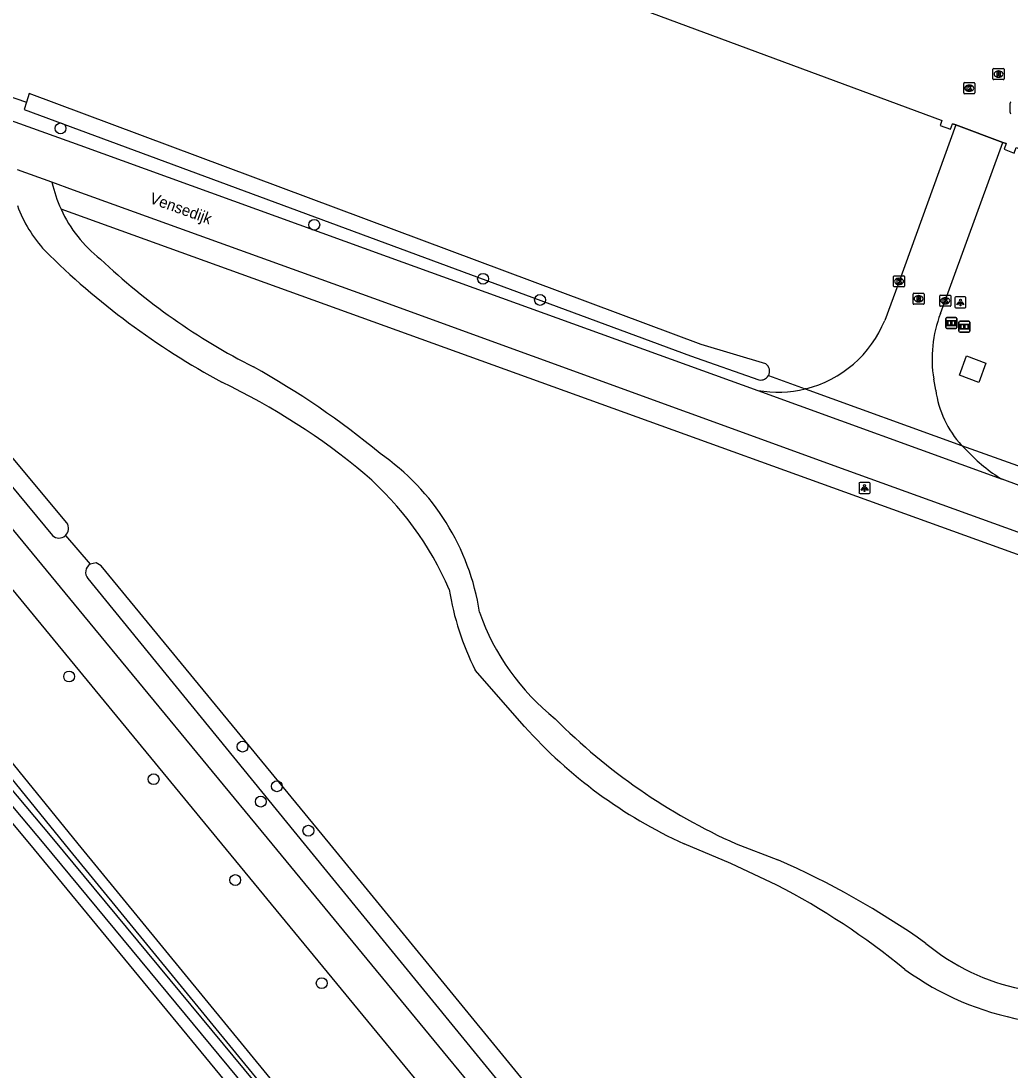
# Model space of a CAD drawing. Extents: x 156061 to 157804, y 383451 to 385640.
# Drawn here: x 156629.3 to 156718.3, y 384979.6 to 385074 of the extents above; entities that cross this region are included whole.
import ezdxf

# ---------------------------------------------------------------- set-up
doc = ezdxf.new("R2010")
doc.units = 0
for name, color, linetype in [('IMGEO_Berm_groen', 7, 'Continuous'), ('IMGEO_Boom', 7, 'Continuous'), ('IMGEO_Fietspad_gesloten', 7, 'Continuous'), ('IMGEO_Grasland_overig', 7, 'Continuous'), ('IMGEO_Groenvoorziening', 7, 'Continuous'), ('IMGEO_Hek', 7, 'Continuous'), ('IMGEO_Informatiebord', 7, 'Continuous'), ('IMGEO_Kolk', 7, 'Continuous'), ('IMGEO_Lage_trafo', 7, 'Continuous'), ('IMGEO_Lichtpunt', 7, 'Continuous'), ('IMGEO_Loofbos', 7, 'Continuous'), ('IMGEO_Openbare_ruimte_label', 7, 'Continuous'), ('IMGEO_Rijbaan_lokaal_open', 7, 'Continuous'), ('IMGEO_Rioolput', 7, 'Continuous'), ('IMGEO_Waterloop', 7, 'Continuous')]:
    doc.layers.add(name, color=color, linetype=linetype)

msp = doc.modelspace()

# ---------------------------------------------------------------- linework, layer by layer
at = {"layer": 'IMGEO_Berm_groen'}
msp.add_lwpolyline([(156633.293, 385027.733), (156635.536, 385025.155)], dxfattribs=at)
at = {"layer": 'IMGEO_Boom'}
for centre in [(156632.856, 385064.382), (156655.692, 385055.706), (156670.884, 385050.847), (156676.018, 385048.942), (156633.634, 385015.06), (156649.236, 385008.753), (156641.232, 385005.82), (156652.326, 385005.179), (156650.88, 385003.8), (156655.162, 385001.18), (156648.58, 384996.739), (156656.369, 384987.464)]:
    msp.add_circle(centre, 0.489, dxfattribs=at)
at = {"layer": 'IMGEO_Fietspad_gesloten'}
for points in [[(156952.011, 384636.1), (156951.649, 384636.454), (156945.248, 384644.122), (156913.262, 384682.917), (156857.952, 384750), (156766.231, 384861.244), (156717.241, 384920.698), (156651.898, 385000), (156634.534, 385021.048), (156628.661, 385028.193), (156628.314, 385028.596), (156616.132, 385043.374), (156611.412, 385049.1), (156600.259, 385062.638)], [(156605.091, 385050.034), (156608.817, 385046.509), (156609.374, 385045.976), (156609.93, 385045.436), (156647.34, 385000), (156714.453, 384918.502), (156763.606, 384858.813), (156853.32, 384750), (156910.525, 384680.616)]]:
    msp.add_lwpolyline(points, dxfattribs=at)
at = {"layer": 'IMGEO_Grasland_overig'}
msp.add_arc((156643.914, 385062.172), 12.118, 192.57556, 204.6773, dxfattribs=at)
at = {"layer": 'IMGEO_Groenvoorziening'}
for points in [[(156717.677, 385063.118), (156717.97, 385063.009), (156717.781, 385062.506), (156718.696, 385062.163), (156718.88, 385062.654), (156870.373, 385006.508), (156870.967, 385006.288), (156875.119, 385016.625), (156892.549, 385064.295), (156865.99, 385088.285), (156852.111, 385101.789), (156804.773, 385147.48), (156780.437, 385174.157), (156759.871, 385196.529)], [(156704.185, 384910.355), (156680.539, 384938.812), (156675.709, 384944.624), (156664.3, 384958.479), (156630.109, 385000), (156603.329, 385032.022), (156590.034, 385048.185), (156581.376, 385058.421), (156579.11, 385060.987), (156576.247, 385063.649), (156574.166, 385065.132), (156572.592, 385066.255), (156568.65, 385068.402), (156563.107, 385070.714), (156551.893, 385074.785), (156500, 385093.06), (156436.131, 385115.542), (156397.25, 385072.572), (156397.423, 385071.829)], [(156566.301, 385089.228), (156607.493, 385074.38), (156629.792, 385066.728)], [(156658.244, 385085.094), (156712.128, 385065.114), (156712.188, 385065.092), (156712.024, 385064.637), (156712.959, 385064.3), (156713.142, 385064.807), (156713.445, 385064.694)], [(156673.482, 384950.407), (156672.799, 384949.599), (156658.27, 384967.539), (156631.387, 385000), (156602.972, 385033.813), (156586.855, 385053.4), (156580.462, 385060.696), (156577.709, 385063.589)], [(156582.153, 385063.43), (156585.552, 385059.831), (156605.373, 385035.73), (156634.41, 385000), (156674.271, 384951.339), (156673.482, 384950.407)], [(156696.567, 385042.138), (156699.886, 385040.939)], [(156713.959, 385035.854), (156720.234, 385033.587)]]:
    msp.add_lwpolyline(points, dxfattribs=at)
at = {"layer": 'IMGEO_Hek'}
for points in [[(156658.244, 385085.094), (156712.128, 385065.114), (156712.188, 385065.092)], [(156713.445, 385064.694), (156713.142, 385064.807)], [(156717.677, 385063.118), (156713.445, 385064.694)], [(156717.97, 385063.009), (156717.677, 385063.118)]]:
    msp.add_lwpolyline(points, dxfattribs=at)
at = {"layer": 'IMGEO_Informatiebord'}
for p, q in [((156712.535, 385046.462), (156712.535, 385047.262)), ((156712.535, 385047.262), (156712.535, 385046.462)), ((156712.635, 385047.362), (156713.425, 385047.362)), ((156713.425, 385047.362), (156712.635, 385047.362)), ((156713.525, 385047.262), (156713.525, 385046.462)), ((156713.525, 385046.462), (156713.525, 385047.262)), ((156713.425, 385046.362), (156712.635, 385046.362)), ((156712.635, 385046.362), (156713.425, 385046.362)), ((156713.712, 385046.139), (156713.712, 385046.939)), ((156713.712, 385046.939), (156713.712, 385046.139)), ((156713.812, 385047.039), (156714.602, 385047.039)), ((156714.602, 385047.039), (156713.812, 385047.039)), ((156714.702, 385046.939), (156714.702, 385046.139)), ((156714.702, 385046.139), (156714.702, 385046.939)), ((156714.602, 385046.039), (156713.812, 385046.039)), ((156713.812, 385046.039), (156714.602, 385046.039))]:
    msp.add_line(p, q, dxfattribs=at)
for points in [[(156712.636, 385047.094), (156713.424, 385047.094), (156713.424, 385046.63), (156712.636, 385046.63), (156712.636, 385047.094)], [(156712.701, 385047.029), (156712.701, 385046.695), (156712.976, 385046.695), (156712.977, 385046.908), (156713.081, 385046.909), (156713.082, 385046.695), (156713.359, 385046.695), (156713.359, 385047.029), (156713.083, 385047.029), (156713.083, 385046.949), (156712.977, 385046.949), (156712.977, 385047.029), (156712.701, 385047.029)], [(156713.813, 385046.771), (156714.601, 385046.771), (156714.601, 385046.307), (156713.813, 385046.307), (156713.813, 385046.771)], [(156713.878, 385046.706), (156713.878, 385046.372), (156714.153, 385046.372), (156714.154, 385046.585), (156714.258, 385046.586), (156714.259, 385046.372), (156714.536, 385046.372), (156714.536, 385046.706), (156714.26, 385046.706), (156714.26, 385046.626), (156714.154, 385046.626), (156714.154, 385046.706), (156713.878, 385046.706)]]:
    msp.add_lwpolyline(points, dxfattribs=at)
for centre, start, end in [((156712.635, 385047.262), 90, 180), ((156712.635, 385047.262), 90, 180), ((156713.425, 385047.262), 0, 90), ((156713.425, 385047.262), 360, 90), ((156712.635, 385046.462), 180, 270), ((156712.635, 385046.462), 180, 270), ((156713.425, 385046.462), 270, 0), ((156713.425, 385046.462), 270, 0), ((156713.812, 385046.939), 90, 180), ((156713.812, 385046.939), 90, 180), ((156714.602, 385046.939), 0, 90), ((156714.602, 385046.939), 360, 90), ((156713.812, 385046.139), 180, 270), ((156713.812, 385046.139), 180, 270), ((156714.602, 385046.139), 270, 0), ((156714.602, 385046.139), 270, 0)]:
    msp.add_arc(centre, 0.1, start, end, dxfattribs=at)
at = {"layer": 'IMGEO_Kolk'}
for p, q in [((156714.145, 385067.574), (156714.145, 385068.426)), ((156714.22, 385068.5), (156715.072, 385068.5)), ((156714.633, 385068.28), (156714.658, 385068.28)), ((156715.146, 385068.426), (156715.146, 385067.574)), ((156715.072, 385067.5), (156714.22, 385067.5)), ((156714.656, 385067.72), (156714.631, 385067.72)), ((156718.312, 385065.807), (156718.312, 385066.659)), ((156707.822, 385050.193), (156707.822, 385051.045)), ((156707.897, 385051.119), (156708.749, 385051.119)), ((156708.823, 385051.045), (156708.823, 385050.193)), ((156708.749, 385050.119), (156707.897, 385050.119)), ((156708.333, 385050.339), (156708.308, 385050.339)), ((156708.31, 385050.899), (156708.335, 385050.899)), ((156711.986, 385048.448), (156711.986, 385049.3)), ((156712.061, 385049.374), (156712.913, 385049.374)), ((156712.474, 385049.154), (156712.499, 385049.154)), ((156712.987, 385049.3), (156712.987, 385048.448)), ((156712.913, 385048.374), (156712.061, 385048.374)), ((156712.497, 385048.594), (156712.472, 385048.594))]:
    msp.add_line(p, q, dxfattribs=at)
for points in [[(156714.145, 385067.574), (156714.145, 385068.426)], [(156714.22, 385068.5), (156715.072, 385068.5)], [(156714.466, 385068.2), (156714.589, 385068.2), (156714.589, 385068.049), (156714.719, 385068.2), (156714.883, 385068.2), (156714.737, 385068.049), (156714.89, 385067.8), (156714.738, 385067.8), (156714.653, 385067.964), (156714.589, 385067.897), (156714.589, 385067.8), (156714.466, 385067.8), (156714.466, 385068.2)], [(156715.146, 385068.426), (156715.146, 385067.574)], [(156715.072, 385067.5), (156714.22, 385067.5)], [(156718.312, 385065.807), (156718.312, 385066.659)], [(156707.822, 385050.193), (156707.822, 385051.045)], [(156707.897, 385051.119), (156708.749, 385051.119)], [(156708.823, 385051.045), (156708.823, 385050.193)], [(156708.749, 385050.119), (156707.897, 385050.119)], [(156708.143, 385050.819), (156708.266, 385050.819), (156708.266, 385050.668), (156708.396, 385050.819), (156708.56, 385050.819), (156708.414, 385050.668), (156708.567, 385050.419), (156708.415, 385050.419), (156708.33, 385050.583), (156708.266, 385050.516), (156708.266, 385050.419), (156708.143, 385050.419), (156708.143, 385050.819)], [(156711.986, 385048.448), (156711.986, 385049.3)], [(156712.061, 385049.374), (156712.913, 385049.374)], [(156712.987, 385049.3), (156712.987, 385048.448)], [(156712.913, 385048.374), (156712.061, 385048.374)], [(156712.307, 385049.074), (156712.43, 385049.074), (156712.43, 385048.923), (156712.56, 385049.074), (156712.724, 385049.074), (156712.578, 385048.923), (156712.731, 385048.674), (156712.579, 385048.674), (156712.494, 385048.838), (156712.43, 385048.771), (156712.43, 385048.674), (156712.307, 385048.674), (156712.307, 385049.074)]]:
    msp.add_lwpolyline(points, dxfattribs=at)
for centre, start, end in [((156714.222, 385068.424), 91.55205, 178.44795), ((156714.222, 385068.424), 91.55205, 178.44795), ((156715.07, 385068.424), 1.55205, 88.44795), ((156715.07, 385068.424), 1.55205, 88.44795), ((156714.222, 385067.576), 181.55205, 268.44795), ((156714.222, 385067.576), 181.55205, 268.44795), ((156715.07, 385067.576), 271.55205, 358.44795), ((156715.07, 385067.576), 271.55205, 358.44795), ((156718.389, 385066.657), 91.55205, 178.44795), ((156718.389, 385066.657), 91.55205, 178.44795), ((156718.389, 385065.809), 181.55205, 268.44795), ((156718.389, 385065.809), 181.55205, 268.44795), ((156707.899, 385051.043), 91.55205, 178.44795), ((156707.899, 385051.043), 91.55205, 178.44795), ((156708.747, 385051.043), 1.55205, 88.44795), ((156708.747, 385051.043), 1.55205, 88.44795), ((156707.899, 385050.195), 181.55205, 268.44795), ((156707.899, 385050.195), 181.55205, 268.44795), ((156708.747, 385050.195), 271.55205, 358.44795), ((156708.747, 385050.195), 271.55205, 358.44795), ((156712.063, 385049.298), 91.55205, 178.44795), ((156712.063, 385049.298), 91.55205, 178.44795), ((156712.911, 385049.298), 1.55205, 88.44795), ((156712.911, 385049.298), 1.55205, 88.44795), ((156712.063, 385048.45), 181.55205, 268.44795), ((156712.063, 385048.45), 181.55205, 268.44795), ((156712.911, 385048.45), 271.55205, 358.44795), ((156712.911, 385048.45), 271.55205, 358.44795)]:
    msp.add_arc(centre, 0.0765, start, end, dxfattribs=at)
for centre, major_axis, ratio, start_param, end_param in [((156714.632, 385068), (-0.387, 0.002), 0.722429, 4.712389, 7.853982), ((156714.657, 385068), (-0.39, 0.002), 0.717154, 1.570796, 4.712389), ((156708.309, 385050.619), (-0.387, 0.002), 0.722429, 4.712389, 7.853982), ((156708.334, 385050.619), (-0.39, 0.002), 0.717154, 1.570796, 4.712389), ((156712.473, 385048.874), (-0.387, 0.002), 0.722429, 4.712389, 7.853982), ((156712.498, 385048.874), (-0.39, 0.002), 0.717154, 1.570796, 4.712389)]:
    msp.add_ellipse(centre, major_axis=major_axis, ratio=ratio, start_param=start_param, end_param=end_param, dxfattribs=at)
at = {"layer": 'IMGEO_Lage_trafo'}
msp.add_lwpolyline([(156716.143, 385043.251), (156715.495, 385041.518), (156713.757, 385042.168), (156714.405, 385043.901), (156716.143, 385043.251)], dxfattribs=at)
at = {"layer": 'IMGEO_Lichtpunt'}
for p, q in [((156713.352, 385049.124), (156713.352, 385048.317)), ((156713.352, 385049.124), (156713.352, 385048.317)), ((156714.254, 385049.219), (156713.446, 385049.219)), ((156714.254, 385049.219), (156713.446, 385049.219)), ((156714.348, 385048.317), (156714.348, 385049.124)), ((156714.348, 385048.317), (156714.348, 385049.124)), ((156713.446, 385048.223), (156714.254, 385048.223)), ((156713.446, 385048.223), (156714.254, 385048.223)), ((156704.721, 385032.426), (156704.721, 385031.619)), ((156704.721, 385032.426), (156704.721, 385031.619)), ((156705.623, 385032.521), (156704.815, 385032.521)), ((156705.623, 385032.521), (156704.815, 385032.521)), ((156705.717, 385031.619), (156705.717, 385032.426)), ((156705.717, 385031.619), (156705.717, 385032.426)), ((156704.815, 385031.525), (156705.623, 385031.525)), ((156704.815, 385031.525), (156705.623, 385031.525))]:
    msp.add_line(p, q, dxfattribs=at)
for points in [[(156713.726, 385048.788), (156713.765, 385048.76), (156713.577, 385048.498), (156713.539, 385048.525), (156713.726, 385048.788)], [(156713.828, 385048.74), (156713.875, 385048.74), (156713.875, 385048.418), (156713.828, 385048.418), (156713.828, 385048.74)], [(156713.938, 385048.76), (156713.976, 385048.787), (156714.163, 385048.525), (156714.124, 385048.497), (156713.938, 385048.76)], [(156705.095, 385032.09), (156705.134, 385032.062), (156704.946, 385031.8), (156704.908, 385031.827), (156705.095, 385032.09)], [(156705.197, 385032.042), (156705.244, 385032.042), (156705.244, 385031.72), (156705.197, 385031.72), (156705.197, 385032.042)], [(156705.307, 385032.062), (156705.345, 385032.089), (156705.532, 385031.827), (156705.493, 385031.799), (156705.307, 385032.062)]]:
    msp.add_lwpolyline(points, dxfattribs=at)
for centre in [(156713.851, 385048.922), (156705.22, 385032.224)]:
    msp.add_circle(centre, 0.0994, dxfattribs=at)
for centre, start, end in [((156713.446, 385049.124), 90, 180), ((156713.446, 385049.124), 90, 180), ((156714.254, 385049.124), 0, 90), ((156714.254, 385049.124), 0, 90), ((156713.446, 385048.317), 180, 270), ((156713.446, 385048.317), 180, 270), ((156714.254, 385048.317), 270, 0), ((156714.254, 385048.317), 270, 360), ((156704.815, 385032.426), 90, 180), ((156704.815, 385032.426), 90, 180), ((156705.623, 385032.426), 0, 90), ((156705.623, 385032.426), 0, 90), ((156704.815, 385031.619), 180, 270), ((156704.815, 385031.619), 180, 270), ((156705.623, 385031.619), 270, 0), ((156705.623, 385031.619), 270, 360)]:
    msp.add_arc(centre, 0.0946, start, end, dxfattribs=at)
at = {"layer": 'IMGEO_Loofbos'}
for points in [[(156799.556, 384996.608), (156756.361, 385012.544), (156632.902, 385057.113)], [(156674.621, 385010.559), (156670.182, 385015.637)], [(156697.315, 384996.29), (156693.188, 384998.237), (156688.978, 385000)], [(156693.651, 385000), (156697.403, 384998.574)]]:
    msp.add_lwpolyline(points, dxfattribs=at)
for centre, radius, start, end in [((156640.277, 385061.528), 12.014, 199.92856, 222.69113), ((156643.961, 385062.187), 12.167, 204.64837, 231.85835), ((156680.809, 385103.134), 70.085, 225.22503, 241.50853), ((156676.67, 385095.125), 58.522, 226.58108, 243.14024), ((156613.824, 384977.458), 74.902, 50.35651, 60.91962), ((156621.297, 384986.787), 60.645, 50.02945, 64.52979), ((156649.497, 385017.591), 21.32, 8.76662, 55.37233), ((156641.331, 385011.478), 28.857, 23.28741, 49.02038), ((156692.369, 385026.818), 24.845, 189.10609, 206.74597), ((156690.616, 385027.857), 21.241, 199.28952, 231.41181), ((156707.158, 385039.76), 43.719, 221.90655, 245.42746), ((156715.911, 385049.614), 54.379, 224.86366, 245.83574), ((156666.635, 384928.442), 76.585, 54.82942, 66.31249), ((156666.692, 384937.194), 66.559, 50.6907, 62.60765), ((156723.144, 385005.922), 19.364, 230.20006, 258.58582), ((156724.179, 385009.804), 26.084, 234.03093, 259.61358)]:
    msp.add_arc(centre, radius, start, end, dxfattribs=at)
at = {"layer": 'IMGEO_Rijbaan_lokaal_open'}
for points in [[(156604.139, 385073.809), (156606.916, 385072.811), (156634.591, 385062.861), (156662.26, 385052.848), (156695.623, 385040.804)], [(156713.445, 385064.694), (156708.324, 385050.618), (156707.035, 385047.107)], [(156713.445, 385064.694), (156717.677, 385063.118)], [(156712.05, 385047.718), (156717.677, 385063.118)], [(156632.086, 385059.534), (156628.997, 385060.649)], [(156799.582, 384998.753), (156796.159, 385000), (156770.015, 385009.525), (156724.41, 385026.088), (156703.574, 385033.623), (156661.061, 385049.074), (156634.022, 385058.832), (156632.086, 385059.534)], [(156711.623, 385040.831), (156711.45, 385041.827)], [(156695.623, 385040.804), (156717.591, 385032.815)], [(156699.931, 385040.95), (156699.908, 385040.944), (156699.886, 385040.939)], [(156699.886, 385040.939), (156713.959, 385035.854)], [(156713.977, 385035.835), (156713.968, 385035.845), (156713.959, 385035.854)], [(156860.328, 384980.642), (156811.247, 384998.672), (156807.534, 385000.027), (156771.273, 385013.259), (156725.727, 385029.794), (156717.591, 385032.815)]]:
    msp.add_lwpolyline(points, dxfattribs=at)
for centre, radius, start, end in [((156722.451, 385043.683), 11.156, 158.79405, 189.57488), ((156697.431, 385051.011), 10.367, 283.95359, 337.87702), ((156697.433, 385051.017), 10.372, 259.94922, 283.67843), ((156720.643, 385042.028), 9.099, 187.55775, 222.72912), ((156721.113, 385042.501), 9.765, 223.04969, 226.95031), ((156725.28, 385045.508), 14.84, 223.11636, 238.79479)]:
    msp.add_arc(centre, radius, start, end, dxfattribs=at)
at = {"layer": 'IMGEO_Rioolput'}
for p, q in [((156716.779, 385068.846), (156716.779, 385069.698)), ((156716.854, 385069.772), (156717.706, 385069.772)), ((156717.29, 385068.992), (156717.265, 385068.992)), ((156717.267, 385069.552), (156717.292, 385069.552)), ((156717.78, 385069.698), (156717.78, 385068.846)), ((156717.706, 385068.772), (156716.854, 385068.772)), ((156709.585, 385048.625), (156709.585, 385049.477)), ((156709.66, 385049.551), (156710.512, 385049.551)), ((156710.073, 385049.331), (156710.098, 385049.331)), ((156710.586, 385049.477), (156710.586, 385048.625)), ((156710.512, 385048.551), (156709.66, 385048.551)), ((156710.096, 385048.771), (156710.071, 385048.771))]:
    msp.add_line(p, q, dxfattribs=at)
for points in [[(156716.779, 385068.846), (156716.779, 385069.698)], [(156716.854, 385069.772), (156717.706, 385069.772)], [(156717.368, 385069.47), (156717.116, 385069.472), (156717.116, 385069.072)], [(156717.116, 385069.072), (156717.24, 385069.072), (156717.24, 385069.234), (156717.251, 385069.234)], [(156717.294, 385069.391), (156717.24, 385069.391), (156717.24, 385069.31)], [(156717.24, 385069.31), (156717.292, 385069.31)], [(156717.298, 385069.205), (156717.369, 385069.072), (156717.509, 385069.072), (156717.444, 385069.198)], [(156717.78, 385069.698), (156717.78, 385068.846)], [(156717.706, 385068.772), (156716.854, 385068.772)], [(156709.585, 385048.625), (156709.585, 385049.477)], [(156709.66, 385049.551), (156710.512, 385049.551)], [(156710.174, 385049.249), (156709.922, 385049.251), (156709.922, 385048.851)], [(156710.1, 385049.17), (156710.046, 385049.17), (156710.046, 385049.089)], [(156710.586, 385049.477), (156710.586, 385048.625)], [(156710.512, 385048.551), (156709.66, 385048.551)], [(156709.922, 385048.851), (156710.046, 385048.851), (156710.046, 385049.013), (156710.057, 385049.013)], [(156710.046, 385049.089), (156710.098, 385049.089)], [(156710.104, 385048.984), (156710.175, 385048.851), (156710.315, 385048.851), (156710.25, 385048.977)]]:
    msp.add_lwpolyline(points, dxfattribs=at)
for centre, radius, start, end in [((156716.856, 385069.696), 0.0765, 91.55205, 178.44795), ((156716.856, 385069.696), 0.0765, 91.55205, 178.44795), ((156717.25, 385069.181), 0.0533, 26.02933, 88.69889), ((156717.276, 385069.499), 0.19, 274.7715, 282.96867), ((156717.3, 385069.295), 0.0964, 77.00612, 93.18647), ((156717.314, 385069.352), 0.0378, 276.66336, 79.67722), ((156717.367, 385069.36), 0.109, 350.36119, 89.41601), ((156717.365, 385069.36), 0.112, 277.58423, 350.98172), ((156717.349, 385069.145), 0.108, 29.51342, 73.79051), ((156717.704, 385069.696), 0.0765, 1.55205, 88.44795), ((156717.704, 385069.696), 0.0765, 1.55205, 88.44795), ((156716.856, 385068.848), 0.0765, 181.55205, 268.44795), ((156716.856, 385068.848), 0.0765, 181.55205, 268.44795), ((156717.704, 385068.848), 0.0765, 271.55205, 358.44795), ((156717.704, 385068.848), 0.0765, 271.55205, 358.44795), ((156709.662, 385049.475), 0.0765, 91.55205, 178.44795), ((156709.662, 385049.475), 0.0765, 91.55205, 178.44795), ((156710.106, 385049.074), 0.0964, 77.00612, 93.18647), ((156710.12, 385049.131), 0.0378, 276.66336, 79.67722), ((156710.173, 385049.139), 0.109, 350.36119, 89.41601), ((156710.171, 385049.139), 0.112, 277.58423, 350.98172), ((156710.51, 385049.475), 0.0765, 1.55205, 88.44795), ((156710.51, 385049.475), 0.0765, 1.55205, 88.44795), ((156709.662, 385048.627), 0.0765, 181.55205, 268.44795), ((156709.662, 385048.627), 0.0765, 181.55205, 268.44795), ((156710.056, 385048.96), 0.0533, 26.02933, 88.69889), ((156710.082, 385049.278), 0.19, 274.7715, 282.96867), ((156710.155, 385048.924), 0.108, 29.51342, 73.79051), ((156710.51, 385048.627), 0.0765, 271.55205, 358.44795), ((156710.51, 385048.627), 0.0765, 271.55205, 358.44795)]:
    msp.add_arc(centre, radius, start, end, dxfattribs=at)
for centre, major_axis, ratio, start_param, end_param in [((156717.266, 385069.272), (-0.387, 0.002), 0.722429, 4.712389, 7.853982), ((156717.291, 385069.272), (-0.39, 0.002), 0.717154, 1.570796, 4.712389), ((156710.072, 385049.051), (-0.387, 0.002), 0.722429, 4.712389, 7.853982), ((156710.097, 385049.051), (-0.39, 0.002), 0.717154, 1.570796, 4.712389)]:
    msp.add_ellipse(centre, major_axis=major_axis, ratio=ratio, start_param=start_param, end_param=end_param, dxfattribs=at)
at = {"layer": 'IMGEO_Waterloop'}
for points in [[(156553.128, 385076.338), (156568.314, 385070.402), (156571, 385069.176), (156573.577, 385067.734), (156576.027, 385066.087), (156578.335, 385064.245), (156581.131, 385061.307), (156587.545, 385053.986), (156603.668, 385034.392), (156632.082, 385000.58), (156658.971, 384968.113), (156672.814, 384951.02), (156673.092, 384951.349), (156633.708, 384999.427), (156604.672, 385035.157), (156584.872, 385059.232), (156581.516, 385062.785), (156578.051, 385065.973), (156576.304, 385067.377), (156574.434, 385068.613), (156572.459, 385069.672), (156570.395, 385070.544), (156566.618, 385072.219), (156553.365, 385077.123)], [(156696.349, 385043.188), (156690.519, 385044.949), (156630.025, 385067.527), (156629.792, 385066.728)], [(156629.792, 385066.728), (156629.599, 385066.068), (156689.552, 385043.906), (156695.717, 385041.754)], [(156633.422, 385028.896), (156618.313, 385046.971)], [(156617.114, 385045.869), (156632.123, 385027.749)], [(156719.856, 384923.789), (156695.13, 384953.541), (156657.082, 385000), (156636.53, 385025.02), (156636.06, 385025.295), (156635.536, 385025.155)], [(156635.313, 385023.868), (156654.794, 385000), (156704.204, 384939.55), (156717.457, 384923.535), (156718.481, 384922.505)]]:
    msp.add_lwpolyline(points, dxfattribs=at)
for centre, radius, start, end in [((156695.873, 385042.542), 0.803, 329.81947, 53.63865), ((156695.873, 385042.541), 0.802, 258.77101, 329.85253), ((156632.716, 385028.386), 0.871, 311.45794, 35.8833), ((156632.717, 385028.385), 0.87, 226.97116, 311.46187), ((156635.974, 385024.416), 0.859, 120.68994, 219.64984)]:
    msp.add_arc(centre, radius, start, end, dxfattribs=at)

# ---------------------------------------------------------------- texts
at = {"layer": 'IMGEO_Openbare_ruimte_label'}
msp.add_text('Vensedijk', height=1, rotation=340.18819, dxfattribs=at).set_placement((156640.795, 385057.695))

doc.saveas('drawing.dxf')
